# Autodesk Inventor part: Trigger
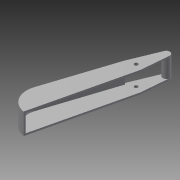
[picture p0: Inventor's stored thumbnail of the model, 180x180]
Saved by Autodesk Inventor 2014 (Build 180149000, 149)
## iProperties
Created: 2009-03
Part Number: Trigger
Document SubType Name: Modeling
Designer: tangg
Density: 7.85 g/cm^3
Material: Steel
Mass: 29.3702 g
Surface Area: 74.34 cm^2
Volume: 3.74142 cm^3
Appearance: Steel
Author: tangg
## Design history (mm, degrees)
sketch "Sketch1"
  geometry: L1 (5, 0)-(6.989, 22.739); L2 (4, 23)-(0, 0); L3 (0, 0)-(-14.032, -80.685); L4 (-18.316, -17.771)-(-22.76, -43.324); L5 (-27.357, -57.698)-(-8.643, 0); L6 (-8.643, 0)-(1.223, 24.135); L7 (-13.913, -80)-(5, 0); A1 r 3 centre (4, 23) between (3.891, 20.002) and (3.827, 20.005); A2 r 17.238 centre (-10.959, -63.016) between (-27.357, -57.698) and (-13.913, -80); 1 further point
  constraints: 14 end point, 6 point on circle, 3 tangent, 2 centre point, 2 horizontal alignment, 2 point on line, 1 coincident, 1 collinear
  dimensions: "d6" = 6 diameter of A1; "d11" = 15 distance between parallel lines of L3 L4; "d23" = 23 vertical distance of point (0, 0) L2.start; "d24" = 8 distance from line of L6 point (0, 0); "d26" = 4 horizontal distance of point (0, 0) L2.start; "d32" = 5 distance of L1.start point (0, 0); "d36" = 80 vertical distance of point (0, 0) L7.start
extrude "Extrusion1" new body sketch "Sketch1" stored distance "d0" = 18; taper "d1" = 0 deg
shell "Shell6" dims "d31" = 1.5
sketch "Sketch2"
  geometry: L1 (4, 23)-(0, 0); C1 r 3 at (4, 23); A1 r 3 centre (4, 23) between (6.989, 22.739) and (1.223, 24.135) reference
  constraints: 2 end point, 1 centre point, 1 coincident, 1 point on line
  dimensions: "d22" = 6 diameter of C1; "d37" = 0 distance of C1.centre L1.start
extrude "Extrusion2" join sketch "Sketch2" stored distance "d14" = 10; taper "d15" = 0 deg
sketch "Sketch3"
  geometry: L1 (4, 23)-(0, 0); C1 r 1.5 at (-1, 2.5); A1 r 3 centre (4, 23) between (7, 23.027) and (2.132, 25.347); A2 r 3 centre (4, 23) between (6.989, 22.739) and (1.223, 24.135) reference
  constraints: 2 centre point, 2 concentric, 2 end point, 2 point on circle
  dimensions: "d33" = 3 diameter of C1; "d34" = 1 horizontal distance of L1.end C1.centre; "d35" = 2.5 vertical distance of L1.end C1.centre
extrude "Extrusion3" cut sketch "Sketch3" stored distance "d18" = 10; taper "d19" = 0 deg
sketch "Sketch4"
  geometry: L1 (1.5, 20.181)-(16.5, 20.181); L2 (16.5, 20.181)-(16.5, 0); L3 (16.5, 0)-(1.5, 0); L4 (1.5, 0)-(1.5, 20.181); L5 (0, 0)-(18, 0) reference; L6 (18, -60.489)-(18, 0) reference; L7 (0, 0)-(18, 0) reference; L8 (0, 0)-(0, -60.489) reference; L9 (0, -60.489)-(18, -60.489) reference; 1 further point
  constraints: 8 end point, 2 parallel, 1 collinear, 1 horizontal, 1 perpendicular
extrude "Extrusion4" cut sketch "Sketch4" stored distance "d38" = 10; taper "d39" = 0 deg
body "Solid1"
node "Projected Loop1"
